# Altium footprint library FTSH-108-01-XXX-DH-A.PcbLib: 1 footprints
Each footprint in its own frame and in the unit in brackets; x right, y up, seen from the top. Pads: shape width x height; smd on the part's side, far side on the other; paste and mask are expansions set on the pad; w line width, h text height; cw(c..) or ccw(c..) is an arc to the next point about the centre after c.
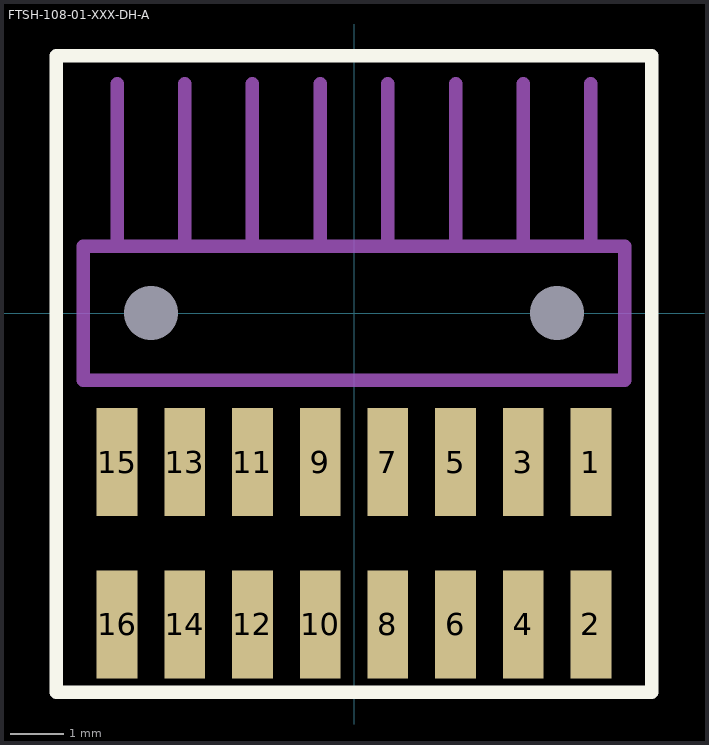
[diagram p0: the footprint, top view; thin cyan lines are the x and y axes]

## FTSH-108-01-XXX-DH-A [mil]
pads (18):
  rect 30x80 smd mask+2: 1(175,-110) 2(175,-230) 3(125,-110) 4(125,-230) 5(75,-110) 6(75,-230) 7(25,-110) 8(25,-230) 9(-25,-110) 10(-25,-230) 11(-75,-110) 12(-75,-230) 13(-125,-110) 14(-125,-230) 15(-175,-110) 16(-175,-230)
  round 0 hole 40 unplated: 17(150,0) 18(-150,0)
Top Overlay:
  lines w10: -220,-280 -220,190 220,190 220,-280 -220,-280
Mechanical 1:
  lines w10: -175,49.5 -175,169.5 ; -125,49.5 -125,169.5 ; -75,49.5 -75,169.5 ; -25,49.5 -25,169.5 ; 25,49.5 25,169.5 ; 75,49.5 75,169.5 ; 125,49.5 125,169.5 ; 175,49.5 175,169.5 ; -200,-49.5 -200,49.5 200,49.5 200,-49.5 -200,-49.5
  text "J1" at -17.57,-18 h30
3D body: height 135, standoff -40, extent -199.99,-259.49 200.01,169.51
